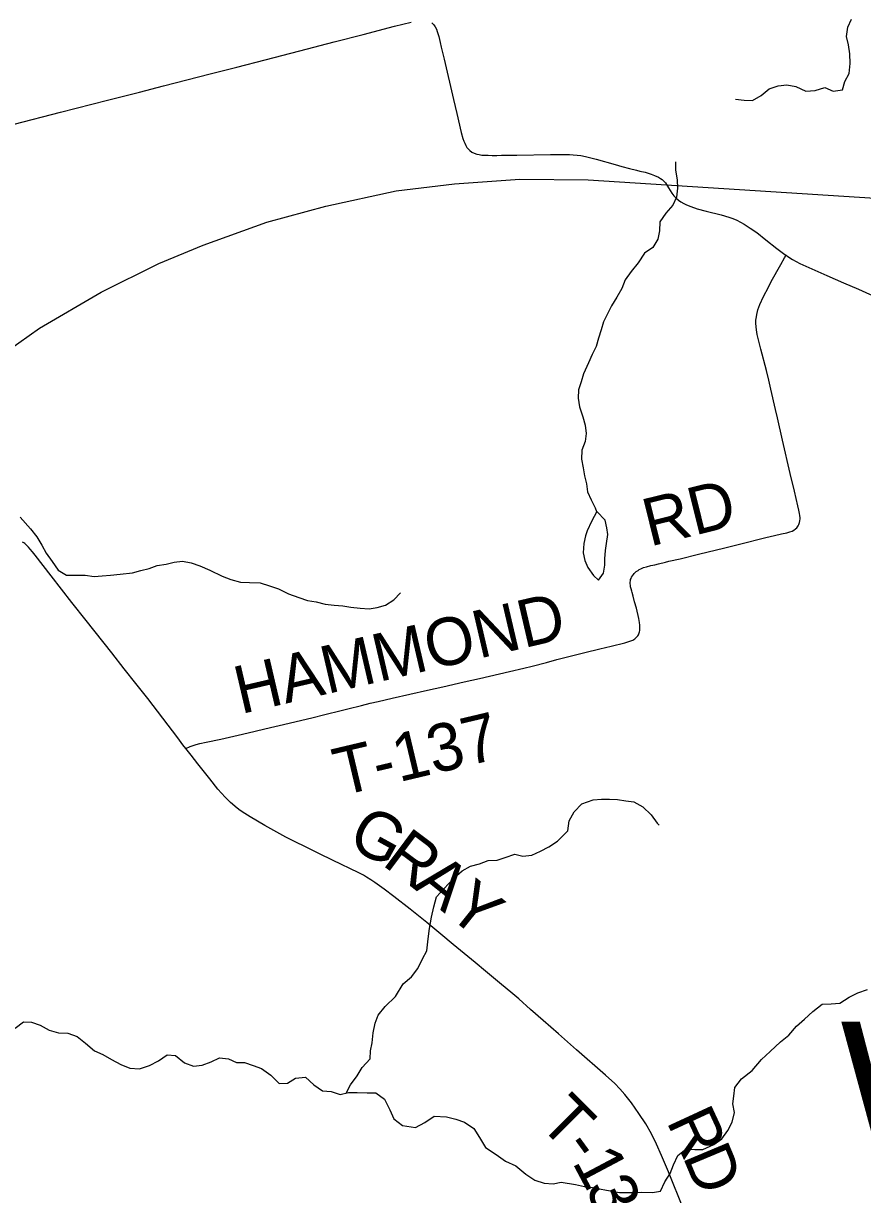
# Model space of a CAD drawing. Extents: x 0 to 1101, y 0 to 440.
# Drawn here: x 377.45 to 407.44, y 167.31 to 209.21 of the extents above; entities that cross this region are included whole.
import ezdxf

# ---------------------------------------------------------------- set-up
doc = ezdxf.new("R2010")
doc.units = 0
for name, color, linetype in [('GM_X_Minor_Lake', 7, 'Continuous'), ('GM_X_Minor_River', 7, 'Continuous'), ('GM_X_Rail_Line', 7, 'Continuous'), ('GM_X_State_Route', 7, 'Continuous'), ('GM_X_Township_Road', 7, 'Continuous'), ('GM_X_Township_Road_Text', 7, 'Continuous'), ('GM_X_Township_Text', 7, 'Continuous')]:
    doc.layers.add(name, color=color, linetype=linetype)

msp = doc.modelspace()

# ---------------------------------------------------------------- linework, layer by layer
at = {"layer": 'GM_X_Minor_Lake'}
for points in [[(397.94, 191.752), (397.749, 191.391), (397.596, 191.052), (397.536, 190.871), (397.475, 190.599), (397.459, 190.269), (397.512, 189.996), (397.622, 189.744), (397.823, 189.457), (398.003, 189.295), (398.122, 189.453)], [(398.122, 189.453), (398.189, 189.543), (398.227, 189.827), (398.231, 190.054), (398.258, 190.349), (398.295, 190.599), (398.334, 190.928), (398.304, 191.167), (398.239, 191.441), (397.94, 191.752)]]:
    msp.add_lwpolyline(points, dxfattribs=at)
at = {"layer": 'GM_X_Minor_River'}
for points in [[(402.904, 206.493), (403.212, 206.456), (403.509, 206.453), (403.819, 206.622), (404.107, 206.87), (404.428, 206.97), (404.736, 207.013), (405.056, 206.953), (405.42, 206.778), (405.751, 206.809), (406.095, 206.909), (406.39, 206.78), (406.722, 206.834), (406.816, 207.13), (406.967, 207.415), (407.005, 207.769), (406.985, 208.112), (406.942, 208.444), (406.865, 208.742), (406.914, 209.073), (407.053, 209.357)], [(400.759, 204.251), (400.757, 203.954), (400.822, 203.611), (400.831, 203.313), (400.794, 202.994), (400.665, 202.709), (400.412, 202.415), (400.192, 202.109), (400.189, 201.789), (400.129, 201.492), (399.944, 201.185), (399.645, 200.983), (399.425, 200.642), (399.171, 200.336), (398.962, 200.03), (398.845, 199.722), (398.66, 199.416), (398.474, 199.098), (398.323, 198.814), (398.183, 198.529), (398.101, 198.245), (398.007, 197.949), (397.924, 197.652), (397.784, 197.368), (397.645, 197.061), (397.47, 196.675), (397.387, 196.39), (397.293, 196.094), (397.279, 195.797), (397.322, 195.488), (397.444, 195.133), (397.533, 194.836), (397.565, 194.538), (397.528, 194.253), (397.411, 193.935), (397.396, 193.615), (397.451, 193.306), (397.505, 193.021), (397.571, 192.734), (397.614, 192.449), (397.737, 192.162), (397.883, 191.875), (397.939, 191.749)], [(377.331, 191.549), (377.704, 191.124), (377.93, 190.836), (378.11, 190.538), (378.267, 190.251), (378.482, 189.963), (378.696, 189.653), (378.991, 189.468), (379.357, 189.464), (379.654, 189.473), (379.973, 189.424), (380.259, 189.444), (380.556, 189.464), (380.91, 189.506), (381.345, 189.548), (381.643, 189.636), (381.94, 189.702), (382.227, 189.813), (382.547, 189.867), (382.833, 189.933), (383.131, 189.975), (383.45, 189.915), (383.757, 189.798), (384.11, 189.646), (384.554, 189.437), (384.861, 189.32), (385.203, 189.214)], [(385.203, 189.214), (385.534, 189.21), (385.911, 189.195), (386.241, 189.089), (386.571, 188.984), (386.924, 188.797), (387.288, 188.669), (387.607, 188.563), (387.915, 188.514), (388.234, 188.431), (388.553, 188.394), (388.862, 188.368), (389.158, 188.319), (389.489, 188.293), (389.809, 188.267), (390.095, 188.31), (390.392, 188.399), (390.691, 188.59), (390.933, 188.838)], [(388.99, 170.943), (389.137, 171.233), (389.38, 171.561), (389.554, 171.855), (389.843, 172.171), (389.857, 172.456), (389.917, 172.74), (389.954, 173.093), (390.026, 173.445), (390.132, 173.729), (390.374, 174.045), (390.743, 174.395), (391.022, 174.848), (391.321, 175.107), (391.552, 175.401), (391.715, 175.741), (391.866, 176.036), (391.916, 176.457), (391.965, 176.833), (392.037, 177.242), (392.121, 177.606), (392.215, 177.958), (392.481, 178.252), (392.839, 178.636), (393.127, 178.895), (393.425, 179.064), (393.746, 179.14), (394.067, 179.262), (394.386, 179.271), (394.673, 179.371), (395.017, 179.493), (395.302, 179.421), (395.622, 179.453), (395.932, 179.598), (396.23, 179.754), (396.54, 179.957), (396.909, 180.329), (396.958, 180.682), (397.132, 181), (397.409, 181.293), (397.81, 181.438), (398.108, 181.458), (398.393, 181.455), (398.679, 181.441), (398.986, 181.392), (399.272, 181.366), (399.59, 181.181), (399.884, 180.893), (400.099, 180.595), (400.178, 180.525)], [(402.878, 171.146), (403.121, 171.451), (403.5, 171.755), (403.835, 172.15), (404.146, 172.432), (404.515, 172.781), (404.803, 173.018), (405.08, 173.334), (405.368, 173.582), (405.667, 173.864), (406.001, 174.122), (406.321, 174.142), (406.63, 174.162), (406.963, 174.375), (407.273, 174.532), (407.617, 174.654)], [(377.151, 173.262), (377.451, 173.498), (377.736, 173.484), (378.043, 173.379), (378.373, 173.193), (378.703, 173.099), (379.034, 173.084), (379.365, 172.967), (379.671, 172.725), (379.988, 172.46), (380.284, 172.32), (380.602, 172.146), (380.932, 171.972), (381.25, 171.833), (381.604, 171.806), (381.959, 171.928), (382.281, 172.096), (382.591, 172.309), (382.888, 172.284), (383.205, 172.03), (383.524, 171.902), (383.833, 171.944), (384.154, 172.067), (384.463, 172.2), (384.783, 172.174), (385.067, 172.035), (385.353, 172.032), (385.66, 171.927), (385.956, 171.821), (386.297, 171.579), (386.591, 171.291), (386.888, 171.3), (387.175, 171.479), (387.53, 171.51), (387.824, 171.234), (388.142, 171.026), (388.45, 171), (388.769, 170.895), (389.066, 170.96), (389.375, 170.968), (389.74, 170.954), (390.049, 170.951), (390.355, 170.731), (390.546, 170.342), (390.691, 170.022), (390.997, 169.78), (391.465, 169.707), (391.798, 169.886), (392.131, 170.122), (392.576, 170.095), (392.907, 170.012), (393.214, 169.907), (393.543, 169.676), (393.746, 169.355), (393.971, 169), (394.346, 168.746), (394.675, 168.504), (395.05, 168.341), (395.413, 168.041), (395.731, 167.833), (396.061, 167.716), (396.38, 167.702), (396.667, 167.756), (397.18, 167.672), (397.51, 167.6), (397.796, 167.563), (398.286, 167.467), (398.753, 167.383), (399.256, 167.39), (399.542, 167.399), (399.93, 167.383), (400.216, 167.438), (400.379, 167.766), (400.565, 168.072), (400.682, 168.378), (400.845, 168.706), (401.144, 168.954), (401.452, 168.928), (401.738, 168.926), (402.128, 169.104), (402.415, 169.306), (402.624, 169.611), (402.786, 169.906), (402.869, 170.247), (402.804, 170.555), (402.841, 170.839), (402.878, 171.146)]]:
    msp.add_lwpolyline(points, dxfattribs=at)
at = {"layer": 'GM_X_Rail_Line'}
msp.add_lwpolyline([(376.533, 197.258), (378.028, 198.307), (380.224, 199.587), (382.295, 200.613), (383.875, 201.27), (386.154, 202.1), (388.264, 202.663), (390.776, 203.211), (392.86, 203.473), (395.199, 203.639), (397.631, 203.614), (413.859, 202.57), (422.761, 201.888), (437.413, 200.804), (442.613, 200.537)], dxfattribs=at)
at = {"layer": 'GM_X_State_Route'}
for points in [[(377.113, 205.604), (378.776, 206.034), (380.456, 206.458), (381.594, 206.749), (382.461, 206.97), (384.121, 207.402), (385.078, 207.646), (386.089, 207.906), (387.334, 208.228), (388.562, 208.543), (389.59, 208.81), (390.708, 209.102), (391.306, 209.254)], [(392.046, 209.225), (392.076, 209.201), (392.109, 209.171), (392.148, 209.119), (392.171, 209.08), (392.209, 209.002), (392.241, 208.922), (392.274, 208.814), (392.292, 208.738), (392.321, 208.629), (392.346, 208.519), (392.387, 208.356), (392.491, 207.921), (392.828, 206.487), (392.946, 205.979), (393.102, 205.307), (393.159, 205.092), (393.19, 204.997), (393.222, 204.918), (393.261, 204.838), (393.3, 204.772), (393.343, 204.719), (393.406, 204.655), (393.477, 204.604), (393.558, 204.562), (393.654, 204.529), (393.739, 204.512), (393.835, 204.497), (393.923, 204.491), (394.066, 204.487), (394.203, 204.485), (394.37, 204.485), (394.54, 204.489), (395.08, 204.495), (396.292, 204.52), (396.778, 204.522), (396.963, 204.517), (397.097, 204.509), (397.244, 204.494), (397.37, 204.48), (397.541, 204.445), (397.923, 204.35), (398.604, 204.154), (398.837, 204.088), (399.109, 204.017), (399.361, 203.956), (399.488, 203.925), (399.67, 203.879), (399.888, 203.814), (400.009, 203.765), (400.145, 203.703), (400.222, 203.66), (400.279, 203.62), (400.322, 203.582), (400.36, 203.54), (400.395, 203.498), (400.51, 203.324), (400.63, 203.134), (400.701, 203.043), (400.771, 202.965), (400.86, 202.886), (400.953, 202.819), (401.05, 202.767), (401.148, 202.717), (401.3, 202.655), (401.528, 202.579), (401.852, 202.492), (402.395, 202.357), (402.665, 202.279), (402.81, 202.226), (402.945, 202.167), (403.082, 202.097), (403.211, 202.026), (403.432, 201.885), (403.66, 201.721), (403.984, 201.467), (404.378, 201.154), (404.66, 200.943), (404.708, 200.91), (404.767, 200.87), (404.94, 200.764), (405.201, 200.622), (405.519, 200.469), (406.166, 200.183), (406.766, 199.928), (407.296, 199.697), (408.197, 199.29)]]:
    msp.add_lwpolyline(points, dxfattribs=at)
at = {"layer": 'GM_X_Township_Road'}
for points in [[(383.258, 183.268), (383.407, 183.336), (383.513, 183.38), (383.627, 183.416), (383.755, 183.45), (383.987, 183.497), (384.501, 183.609), (385.284, 183.781), (385.738, 183.885), (386.081, 183.97), (386.95, 184.181), (387.801, 184.383), (388.181, 184.474), (388.849, 184.64), (389.048, 184.689), (389.536, 184.811), (389.844, 184.886), (390.134, 184.954), (390.625, 185.066), (391.898, 185.352), (392.443, 185.476), (393.207, 185.649), (393.752, 185.773), (394.827, 186.021), (395.331, 186.137), (395.637, 186.217), (396.142, 186.351), (396.521, 186.45), (397.513, 186.703), (398.056, 186.837), (398.456, 186.929), (398.95, 187.047), (399.092, 187.091), (399.191, 187.128), (399.235, 187.15), (399.266, 187.167), (399.309, 187.197), (399.343, 187.224), (399.378, 187.261), (399.407, 187.298), (399.429, 187.334), (399.446, 187.371), (399.47, 187.441), (399.479, 187.492), (399.484, 187.549), (399.487, 187.606), (399.486, 187.68), (399.475, 187.777), (399.451, 187.922), (399.363, 188.286), (399.297, 188.521), (399.242, 188.719), (399.208, 188.844), (399.192, 188.898), (399.17, 188.977), (399.152, 189.058), (399.144, 189.116), (399.141, 189.161), (399.14, 189.222), (399.144, 189.265), (399.154, 189.316), (399.169, 189.355), (399.189, 189.403), (399.218, 189.449), (399.251, 189.494), (399.282, 189.531), (399.313, 189.563), (399.357, 189.598), (399.418, 189.64), (399.463, 189.667), (399.515, 189.694), (399.617, 189.738), (399.725, 189.773), (399.871, 189.811), (400.013, 189.845), (400.144, 189.875), (400.399, 189.934), (400.525, 189.966), (400.925, 190.058), (401.577, 190.216), (402.516, 190.452), (403.04, 190.583), (403.982, 190.813), (404.291, 190.885), (404.547, 190.942), (404.731, 190.983), (404.84, 191.017), (404.925, 191.048), (404.988, 191.084), (405.042, 191.123), (405.09, 191.162), (405.122, 191.201), (405.144, 191.235), (405.168, 191.279), (405.183, 191.321), (405.193, 191.357), (405.202, 191.41), (405.21, 191.482), (405.21, 191.526), (405.205, 191.6), (405.192, 191.679), (405.165, 191.799), (405.132, 191.944), (405.006, 192.47), (404.853, 193.104), (404.578, 194.303), (404.398, 195.102), (404.331, 195.392), (404.166, 196.119), (404.089, 196.445), (404.005, 196.788), (403.806, 197.559), (403.682, 198.082), (403.653, 198.242), (403.638, 198.355), (403.629, 198.481), (403.633, 198.595), (403.647, 198.714), (403.663, 198.797), (403.687, 198.897), (403.706, 198.957), (403.739, 199.055), (403.774, 199.151), (403.903, 199.44), (404.077, 199.768), (404.181, 199.978), (404.523, 200.585), (404.656, 200.818), (404.708, 200.91)], [(383.258, 183.268), (383.153, 183.403), (382.964, 183.646), (381.895, 185.053), (381.469, 185.594), (381.056, 186.121), (380.609, 186.693), (379.691, 187.844), (379.185, 188.489), (378.44, 189.444), (377.87, 190.183), (377.773, 190.303), (377.695, 190.401), (377.632, 190.474), (377.571, 190.534), (377.5, 190.599), (377.46, 190.626), (377.414, 190.651)], [(401.045, 166.796), (400.503, 168.124), (400.26, 168.709), (400.08, 169.118), (399.896, 169.483), (399.692, 169.839), (399.451, 170.215), (399.181, 170.594), (398.952, 170.889), (398.767, 171.098), (398.585, 171.284), (398.256, 171.587), (397.22, 172.496), (396.575, 173.06), (396.028, 173.538), (395.579, 173.931), (395.152, 174.319), (394.938, 174.499), (394.463, 174.889), (393.963, 175.308), (393.593, 175.62), (392.815, 176.258), (392.37, 176.626), (391.869, 177.043), (391.272, 177.519), (390.687, 177.979), (390.347, 178.239), (390.013, 178.476), (389.867, 178.57), (389.715, 178.665), (389.602, 178.733), (389.439, 178.82), (388.5, 179.275), (388.031, 179.503), (387.529, 179.748), (387.162, 179.931), (386.832, 180.101), (386.083, 180.515), (385.553, 180.825), (385.271, 181.006), (385.145, 181.093), (385.015, 181.193), (384.922, 181.275), (384.847, 181.339), (384.75, 181.436), (384.663, 181.524), (384.403, 181.817), (384.111, 182.179), (383.689, 182.725), (383.447, 183.03), (383.258, 183.268)]]:
    msp.add_lwpolyline(points, dxfattribs=at)

# ---------------------------------------------------------------- texts
at = {"layer": 'GM_X_Township_Road_Text'}
for s, height, rotation, p in [('RD', 1.7045, 13.9197, (399.838, 190.488)), ('HAMMOND', 1.7045, 13.1245, (385.218, 184.496)), ('T-137', 1.7045, 13.367, (388.775, 181.564)), ('G', 1.705, 331.2727, (388.964, 179.82)), ('R', 1.705, 323.2308, (390.226, 179.133)), ('A', 1.705, 321.3442, (391.336, 178.304)), ('Y', 1.705, 321.2924, (392.507, 177.367)), ('T', 1.705, 315.0879, (395.814, 169.84)), ('R', 1.705, 294.8403, (400.417, 169.943)), ('-', 1.705, 305.9315, (396.67, 168.994)), ('1', 1.705, 297.9709, (397.048, 168.481)), ('D', 1.705, 292.7566, (400.999, 168.688)), ('3', 1.705, 292.7011, (397.522, 167.591))]:
    msp.add_text(s, height=height, rotation=rotation, dxfattribs=at).set_placement(p)
at = {"layer": 'GM_X_Township_Text'}
msp.add_text('WAYNE', height=5.1136, rotation=0, dxfattribs=at).set_placement((406.655, 168.38))

doc.saveas('drawing.dxf')
